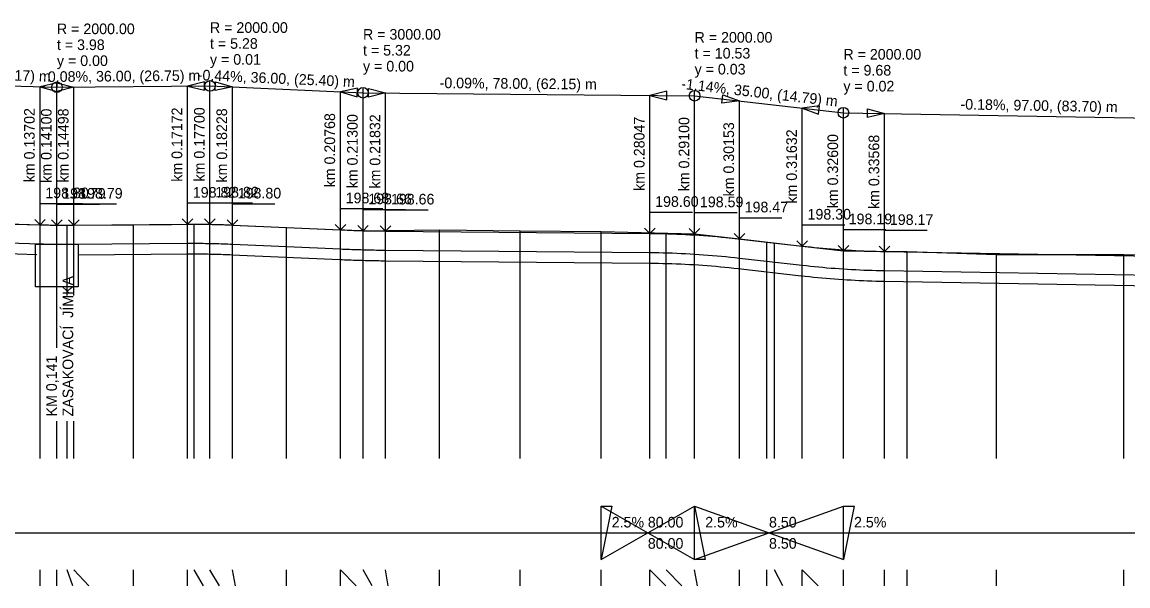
# Model space of a CAD drawing. Extents: x -51 to 53, y -74 to 15.
# Drawn here: x -25.16 to 0.85, y -60.55 to -47.28 of the extents above; entities that cross this region are included whole.
import ezdxf

# ---------------------------------------------------------------- set-up
doc = ezdxf.new("R2010")
doc.units = 0
for name, color, linetype in [('KONSTRUKCE_L', 7, 'Continuous'), ('KOTY_L', 7, 'Continuous'), ('Nová vrstva (0)', 7, 'Continuous'), ('PR_SKLON_L', 7, 'Continuous'), ('PR_SKLON_T', 7, 'Continuous'), ('SKLON_POMERY', 7, 'Continuous'), ('TEREN_L', 7, 'Continuous'), ('V_POLYGON', 7, 'Continuous'), ('V_POLYGON_ZO', 7, 'Continuous')]:
    doc.layers.add(name, color=color, linetype=linetype)

msp = doc.modelspace()

# ---------------------------------------------------------------- linework, layer by layer
at = {"layer": 'KONSTRUKCE_L'}
for p, q in [((-26.854, -52.432), (-24.738, -52.499)), ((-24.738, -52.499), (-24.698, -52.5)), ((-24.698, -52.5), (-24.658, -52.501)), ((-24.658, -52.501), (-24.618, -52.502)), ((-24.618, -52.502), (-24.579, -52.503)), ((-24.579, -52.503), (-24.539, -52.504)), ((-24.539, -52.504), (-24.499, -52.505)), ((-24.499, -52.505), (-24.459, -52.505)), ((-24.459, -52.505), (-24.42, -52.506)), ((-24.42, -52.506), (-24.38, -52.507)), ((-24.38, -52.507), (-24.34, -52.507)), ((-24.34, -52.507), (-24.3, -52.508)), ((-24.3, -52.508), (-24.26, -52.508)), ((-24.26, -52.508), (-24.221, -52.508)), ((-24.221, -52.508), (-24.181, -52.508)), ((-24.181, -52.508), (-24.141, -52.509)), ((-24.141, -52.509), (-24.101, -52.509)), ((-24.101, -52.509), (-24.062, -52.509)), ((-24.062, -52.509), (-24.022, -52.508)), ((-24.022, -52.508), (-23.982, -52.508)), ((-23.982, -52.508), (-23.942, -52.508)), ((-23.942, -52.508), (-21.268, -52.486)), ((-21.268, -52.486), (-21.215, -52.485)), ((-21.215, -52.485), (-21.162, -52.485)), ((-21.162, -52.485), (-21.109, -52.485)), ((-21.109, -52.485), (-21.057, -52.485)), ((-21.057, -52.485), (-21.004, -52.485)), ((-21.004, -52.485), (-20.951, -52.485)), ((-20.951, -52.485), (-20.898, -52.486)), ((-20.898, -52.486), (-20.846, -52.487)), ((-20.846, -52.487), (-20.793, -52.487)), ((-20.793, -52.487), (-20.74, -52.488)), ((-20.74, -52.488), (-20.687, -52.489)), ((-20.687, -52.489), (-20.634, -52.49)), ((-20.634, -52.49), (-20.582, -52.492)), ((-20.582, -52.492), (-20.529, -52.493)), ((-20.529, -52.493), (-20.476, -52.495)), ((-20.476, -52.495), (-20.423, -52.496)), ((-20.423, -52.496), (-20.371, -52.498)), ((-20.371, -52.498), (-20.318, -52.5)), ((-20.318, -52.5), (-20.265, -52.502)), ((-20.265, -52.502), (-20.212, -52.505)), ((-20.212, -52.505), (-17.672, -52.618)), ((-17.672, -52.618), (-17.619, -52.62)), ((-17.619, -52.62), (-17.566, -52.622)), ((-17.566, -52.622), (-17.512, -52.624)), ((-17.512, -52.624), (-17.459, -52.626)), ((-17.459, -52.626), (-17.406, -52.628)), ((-17.406, -52.628), (-17.353, -52.63)), ((-17.353, -52.63), (-17.3, -52.632)), ((-17.3, -52.632), (-17.246, -52.633)), ((-17.246, -52.633), (-17.193, -52.635)), ((-17.193, -52.635), (-17.14, -52.636)), ((-17.14, -52.636), (-17.087, -52.638)), ((-17.087, -52.638), (-17.034, -52.639)), ((-17.034, -52.639), (-16.98, -52.64)), ((-16.98, -52.64), (-16.927, -52.641)), ((-16.927, -52.641), (-16.874, -52.642)), ((-16.874, -52.642), (-16.821, -52.643)), ((-16.821, -52.643), (-16.768, -52.644)), ((-16.768, -52.644), (-16.714, -52.645)), ((-16.714, -52.645), (-16.661, -52.645)), ((-16.661, -52.645), (-16.608, -52.646)), ((-16.608, -52.646), (-10.393, -52.702)), ((-10.393, -52.702), (-10.288, -52.703)), ((-10.288, -52.703), (-10.182, -52.705)), ((-10.182, -52.705), (-10.077, -52.707)), ((-10.077, -52.707), (-9.972, -52.71)), ((-9.972, -52.71), (-9.867, -52.713)), ((-9.867, -52.713), (-9.761, -52.717)), ((-9.761, -52.717), (-9.656, -52.722)), ((-9.656, -52.722), (-9.551, -52.727)), ((-9.551, -52.727), (-9.445, -52.733)), ((-9.445, -52.733), (-9.34, -52.739)), ((-9.34, -52.739), (-9.235, -52.746)), ((-9.235, -52.746), (-9.129, -52.753)), ((-9.129, -52.753), (-9.024, -52.761)), ((-9.024, -52.761), (-8.919, -52.769)), ((-8.919, -52.769), (-8.813, -52.778)), ((-8.813, -52.778), (-8.708, -52.788)), ((-8.708, -52.788), (-8.603, -52.798)), ((-8.603, -52.798), (-8.498, -52.809)), ((-8.498, -52.809), (-8.392, -52.82)), ((-8.392, -52.82), (-8.287, -52.832)), ((-8.287, -52.832), (-6.808, -53.001)), ((-6.808, -53.001), (-6.711, -53.011)), ((-6.711, -53.011), (-6.614, -53.022)), ((-6.614, -53.022), (-6.517, -53.032)), ((-6.517, -53.032), (-6.421, -53.041)), ((-6.421, -53.041), (-6.324, -53.05)), ((-6.324, -53.05), (-6.227, -53.059)), ((-6.227, -53.059), (-6.13, -53.067)), ((-6.13, -53.067), (-6.034, -53.074)), ((-6.034, -53.074), (-5.937, -53.081)), ((-5.937, -53.081), (-5.84, -53.088)), ((-5.84, -53.088), (-5.743, -53.094)), ((-5.743, -53.094), (-5.646, -53.1)), ((-5.646, -53.1), (-5.55, -53.105)), ((-5.55, -53.105), (-5.453, -53.11)), ((-5.453, -53.11), (-5.356, -53.114)), ((-5.356, -53.114), (-5.259, -53.118)), ((-5.259, -53.118), (-5.163, -53.121)), ((-5.163, -53.121), (-5.066, -53.124)), ((-5.066, -53.124), (-4.969, -53.126)), ((-4.969, -53.126), (-4.872, -53.128)), ((-4.872, -53.128), (3.497, -53.275))]:
    msp.add_line(p, q, dxfattribs=at)
at = {"layer": 'KOTY_L'}
for p, q in [((-24.738, -57.551), (-24.738, -52.052)), ((-24.34, -54.944), (-24.34, -52.061)), ((-24.101, -53.716), (-24.101, -52.06)), ((-23.942, -53.716), (-23.942, -52.059)), ((-22.54, -57.551), (-22.54, -52.051)), ((-21.268, -57.551), (-21.268, -52.037)), ((-21.109, -57.551), (-21.109, -52.035)), ((-20.74, -57.551), (-20.74, -52.031)), ((-20.212, -57.551), (-20.212, -52.055)), ((-18.94, -57.551), (-18.94, -52.111)), ((-17.672, -57.551), (-17.672, -52.168)), ((-17.672, -57.551), (-17.672, -52.168)), ((-17.14, -57.551), (-17.14, -52.191)), ((-16.608, -57.551), (-16.608, -52.185)), ((-15.34, -57.551), (-15.34, -52.171)), ((-13.44, -57.551), (-13.44, -52.191)), ((-11.54, -57.551), (-11.54, -52.211)), ((-10.393, -57.551), (-10.393, -52.237)), ((-10.393, -57.551), (-10.393, -52.237)), ((-10.01, -57.551), (-10.01, -52.246)), ((-9.34, -57.551), (-9.34, -52.261)), ((-8.287, -57.551), (-8.287, -52.385)), ((-7.64, -57.551), (-7.64, -52.461)), ((-7.462, -57.551), (-7.462, -52.481)), ((-6.808, -57.551), (-6.808, -52.554)), ((-6.808, -57.551), (-6.808, -52.554)), ((-5.84, -57.551), (-5.84, -52.661)), ((-4.872, -57.551), (-4.872, -52.674)), ((-4.34, -57.551), (-4.34, -52.681)), ((-2.24, -57.551), (-2.24, -52.751)), ((0.76, -57.551), (0.76, -52.751)), ((-24.34, -57.551), (-24.34, -56.675)), ((-24.101, -57.551), (-24.101, -56.675)), ((-23.942, -57.551), (-23.942, -56.675)), ((-24.738, -60.551), (-24.738, -60.176)), ((-24.34, -60.551), (-24.34, -60.176)), ((-23.965, -60.551), (-24.101, -60.176)), ((-23.59, -60.551), (-23.942, -60.176)), ((-22.54, -60.551), (-22.54, -60.176)), ((-21.268, -60.551), (-21.268, -60.176)), ((-20.893, -60.551), (-21.109, -60.176)), ((-20.518, -60.551), (-20.74, -60.176)), ((-20.143, -60.551), (-20.212, -60.176)), ((-18.94, -60.551), (-18.94, -60.176)), ((-17.672, -60.551), (-17.672, -60.176)), ((-17.297, -60.551), (-17.672, -60.176)), ((-16.922, -60.551), (-17.14, -60.176)), ((-16.547, -60.551), (-16.608, -60.176)), ((-15.34, -60.551), (-15.34, -60.176)), ((-13.44, -60.551), (-13.44, -60.176)), ((-11.54, -60.551), (-11.54, -60.176)), ((-10.393, -60.551), (-10.393, -60.176)), ((-10.018, -60.551), (-10.393, -60.176)), ((-9.643, -60.551), (-10.01, -60.176)), ((-9.268, -60.551), (-9.34, -60.176)), ((-8.287, -60.551), (-8.287, -60.176)), ((-7.64, -60.551), (-7.64, -60.176)), ((-7.265, -60.551), (-7.462, -60.176)), ((-6.808, -60.551), (-6.808, -60.176)), ((-6.433, -60.551), (-6.808, -60.176)), ((-5.84, -60.551), (-5.84, -60.176)), ((-4.872, -60.551), (-4.872, -60.176)), ((-4.34, -60.551), (-4.34, -60.176)), ((-2.24, -60.551), (-2.24, -60.176)), ((0.76, -60.551), (0.76, -60.176))]:
    msp.add_line(p, q, dxfattribs=at)
at = {"layer": 'Nová vrstva (0)'}
for p, q in [((-26.862, -52.682), (-24.816, -52.746)), ((-23.842, -52.757), (-21.266, -52.736)), ((-21.266, -52.736), (-21.213, -52.735)), ((-21.214, -52.735), (-21.161, -52.735)), ((-21.162, -52.735), (-21.109, -52.735)), ((-21.11, -52.735), (-21.057, -52.735)), ((-21.058, -52.735), (-21.005, -52.735)), ((-21.005, -52.735), (-20.953, -52.735)), ((-20.953, -52.735), (-20.901, -52.736)), ((-20.901, -52.736), (-20.848, -52.737)), ((-20.849, -52.737), (-20.796, -52.737)), ((-20.797, -52.737), (-20.744, -52.738)), ((-20.745, -52.738), (-20.692, -52.739)), ((-20.693, -52.739), (-20.64, -52.74)), ((-20.641, -52.74), (-20.588, -52.742)), ((-20.588, -52.742), (-20.536, -52.743)), ((-20.536, -52.743), (-20.484, -52.745)), ((-20.484, -52.745), (-20.431, -52.746)), ((-20.432, -52.746), (-20.379, -52.748)), ((-20.38, -52.748), (-20.327, -52.75)), ((-20.328, -52.75), (-20.275, -52.752)), ((-20.276, -52.752), (-20.223, -52.754)), ((-20.223, -52.754), (-17.683, -52.867)), ((-17.683, -52.867), (-17.63, -52.87)), ((-17.629, -52.87), (-17.576, -52.872)), ((-17.576, -52.872), (-17.522, -52.874)), ((-17.522, -52.874), (-17.469, -52.876)), ((-17.468, -52.876), (-17.415, -52.878)), ((-17.415, -52.878), (-17.361, -52.88)), ((-17.361, -52.88), (-17.308, -52.882)), ((-17.307, -52.882), (-17.254, -52.883)), ((-17.254, -52.883), (-17.201, -52.885)), ((-17.2, -52.885), (-17.147, -52.886)), ((-17.146, -52.886), (-17.093, -52.888)), ((-17.093, -52.888), (-17.04, -52.889)), ((-17.039, -52.889), (-16.986, -52.89)), ((-16.986, -52.89), (-16.932, -52.891)), ((-16.932, -52.891), (-16.879, -52.892)), ((-16.878, -52.892), (-16.825, -52.893)), ((-16.825, -52.893), (-16.771, -52.894)), ((-16.771, -52.894), (-16.718, -52.895)), ((-16.717, -52.895), (-16.664, -52.895)), ((-16.664, -52.895), (-16.61, -52.896)), ((-16.61, -52.896), (-10.395, -52.952)), ((-10.396, -52.952), (-10.291, -52.953)), ((-10.292, -52.953), (-10.187, -52.955)), ((-10.188, -52.955), (-10.083, -52.957)), ((-10.084, -52.957), (-9.979, -52.96)), ((-9.98, -52.96), (-9.875, -52.963)), ((-9.876, -52.963), (-9.771, -52.967)), ((-9.772, -52.967), (-9.667, -52.972)), ((-9.668, -52.972), (-9.563, -52.977)), ((-9.564, -52.977), (-9.459, -52.982)), ((-9.46, -52.982), (-9.355, -52.988)), ((-9.356, -52.988), (-9.251, -52.995)), ((-9.252, -52.995), (-9.147, -53.002)), ((-9.148, -53.002), (-9.043, -53.01)), ((-9.044, -53.01), (-8.939, -53.019)), ((-8.94, -53.018), (-8.835, -53.027)), ((-8.836, -53.027), (-8.731, -53.037)), ((-8.732, -53.037), (-8.627, -53.047)), ((-8.628, -53.047), (-8.523, -53.057)), ((-8.524, -53.057), (-8.419, -53.068)), ((-8.42, -53.068), (-8.315, -53.08)), ((-8.315, -53.08), (-6.836, -53.249)), ((-6.835, -53.249), (-6.739, -53.26)), ((-6.737, -53.26), (-6.641, -53.27)), ((-6.639, -53.27), (-6.543, -53.28)), ((-6.542, -53.28), (-6.445, -53.29)), ((-6.444, -53.29), (-6.347, -53.299)), ((-6.346, -53.299), (-6.249, -53.308)), ((-6.248, -53.308), (-6.151, -53.316)), ((-6.15, -53.316), (-6.053, -53.323)), ((-6.052, -53.323), (-5.955, -53.331)), ((-5.954, -53.331), (-5.857, -53.337)), ((-5.856, -53.337), (-5.759, -53.343)), ((-5.758, -53.343), (-5.661, -53.349)), ((-5.66, -53.349), (-5.563, -53.354)), ((-5.562, -53.355), (-5.465, -53.359)), ((-5.464, -53.359), (-5.367, -53.364)), ((-5.366, -53.364), (-5.269, -53.367)), ((-5.268, -53.367), (-5.171, -53.371)), ((-5.17, -53.371), (-5.073, -53.374)), ((-5.072, -53.374), (-4.975, -53.376)), ((-4.974, -53.376), (-4.877, -53.378)), ((-4.877, -53.378), (3.493, -53.525))]:
    msp.add_line(p, q, dxfattribs=at)
msp.add_lwpolyline([(-24.84, -52.508), (-23.84, -52.508), (-23.84, -53.508), (-24.84, -53.508)], close=True, dxfattribs=at)
at = {"layer": 'PR_SKLON_L'}
for p, q in [((-11.54, -59.926), (-9.34, -58.676)), ((-11.54, -58.676), (-9.34, -59.926)), ((-9.34, -59.926), (-5.84, -58.676)), ((-9.34, -58.676), (-5.84, -59.926)), ((-38.44, -59.301), (-11.54, -59.301)), ((-11.54, -59.301), (-9.34, -59.301)), ((-9.34, -59.301), (-5.84, -59.301)), ((-5.84, -59.301), (3.86, -59.301)), ((-9.34, -59.926), (-9.34, -59.926)), ((-5.84, -59.926), (-5.84, -59.926))]:
    msp.add_line(p, q, dxfattribs=at)
for points in [[(-11.54, -59.301), (-11.54, -58.676), (-11.29, -58.676), (-11.54, -59.926)], [(-9.34, -59.301), (-9.34, -58.676), (-9.09, -59.926), (-9.34, -59.926)], [(-5.84, -59.301), (-5.84, -58.676), (-5.59, -58.676), (-5.84, -59.926)]]:
    msp.add_lwpolyline(points, close=True, dxfattribs=at)
at = {"layer": 'SKLON_POMERY'}
for p, q in [((-27.84, -48.701), (-24.34, -48.811)), ((-24.738, -52.049), (-24.738, -48.799)), ((-24.34, -48.811), (-24.34, -48.686)), ((-24.34, -48.811), (-20.74, -48.781)), ((-24.34, -52.061), (-24.34, -48.811)), ((-23.942, -52.058), (-23.942, -48.808)), ((-21.268, -52.036), (-21.268, -48.786)), ((-20.74, -48.781), (-20.74, -48.656)), ((-20.74, -52.031), (-20.74, -48.781)), ((-20.74, -48.781), (-17.14, -48.941)), ((-20.212, -52.055), (-20.212, -48.805)), ((-17.14, -48.941), (-17.14, -48.816)), ((-9.34, -49.011), (-9.34, -48.886)), ((-17.672, -52.168), (-17.672, -48.918)), ((-17.14, -52.191), (-17.14, -48.941)), ((-17.14, -48.941), (-9.34, -49.011)), ((-16.608, -52.196), (-16.608, -48.946)), ((-10.393, -52.252), (-10.393, -49.002)), ((-9.34, -52.261), (-9.34, -49.011)), ((-9.34, -49.011), (-5.84, -49.411)), ((-8.287, -52.382), (-8.287, -49.132)), ((-6.808, -52.551), (-6.808, -49.301)), ((-5.84, -49.411), (-5.84, -49.286)), ((-5.84, -52.661), (-5.84, -49.411)), ((-5.84, -49.411), (3.86, -49.581)), ((-4.872, -52.678), (-4.872, -49.428))]:
    msp.add_line(p, q, dxfattribs=at)
for points in [[(-24.738, -48.799), (-24.341, -48.911), (-24.335, -48.711), (-24.738, -48.799)], [(-23.942, -48.808), (-24.342, -48.911), (-24.343, -48.711), (-23.942, -48.808)], [(-21.268, -48.786), (-20.867, -48.882), (-20.869, -48.682), (-21.268, -48.786)], [(-20.212, -48.805), (-20.616, -48.887), (-20.607, -48.687), (-20.212, -48.805)], [(-17.672, -48.918), (-17.277, -49.035), (-17.268, -48.835), (-17.672, -48.918)], [(-16.608, -48.946), (-17.009, -49.042), (-17.007, -48.842), (-16.608, -48.946)], [(-10.393, -49.002), (-9.994, -49.105), (-9.992, -48.905), (-10.393, -49.002)], [(-8.287, -49.132), (-8.696, -49.185), (-8.673, -48.987), (-8.287, -49.132)], [(-6.808, -49.301), (-6.422, -49.445), (-6.399, -49.247), (-6.808, -49.301)], [(-4.872, -49.428), (-5.274, -49.521), (-5.271, -49.321), (-4.872, -49.428)]]:
    msp.add_lwpolyline(points, close=True, dxfattribs=at)
for points in [[(-24.863, -51.924), (-24.738, -52.049), (-24.613, -51.924), (-24.738, -52.049), (-24.738, -51.549), (-23.738, -51.549)], [(-24.465, -51.936), (-24.34, -52.061), (-24.215, -51.936), (-24.34, -52.061), (-24.34, -51.561), (-23.34, -51.561)], [(-24.067, -51.933), (-23.942, -52.058), (-23.817, -51.933), (-23.942, -52.058), (-23.942, -51.558), (-22.942, -51.558)], [(-21.393, -51.911), (-21.268, -52.036), (-21.143, -51.911), (-21.268, -52.036), (-21.268, -51.536), (-20.268, -51.536)], [(-20.865, -51.906), (-20.74, -52.031), (-20.615, -51.906), (-20.74, -52.031), (-20.74, -51.531), (-19.74, -51.531)], [(-20.337, -51.93), (-20.212, -52.055), (-20.087, -51.93), (-20.212, -52.055), (-20.212, -51.555), (-19.212, -51.555)], [(-17.797, -52.043), (-17.672, -52.168), (-17.547, -52.043), (-17.672, -52.168), (-17.672, -51.668), (-16.672, -51.668)], [(-17.265, -52.066), (-17.14, -52.191), (-17.015, -52.066), (-17.14, -52.191), (-17.14, -51.691), (-16.14, -51.691)], [(-16.733, -52.071), (-16.608, -52.196), (-16.483, -52.071), (-16.608, -52.196), (-16.608, -51.696), (-15.608, -51.696)], [(-10.518, -52.127), (-10.393, -52.252), (-10.268, -52.127), (-10.393, -52.252), (-10.393, -51.752), (-9.393, -51.752)], [(-9.465, -52.136), (-9.34, -52.261), (-9.215, -52.136), (-9.34, -52.261), (-9.34, -51.761), (-8.34, -51.761)], [(-8.412, -52.257), (-8.287, -52.382), (-8.162, -52.257), (-8.287, -52.382), (-8.287, -51.882), (-7.287, -51.882)], [(-6.933, -52.426), (-6.808, -52.551), (-6.683, -52.426), (-6.808, -52.551), (-6.808, -52.051), (-5.808, -52.051)], [(-5.965, -52.536), (-5.84, -52.661), (-5.715, -52.536), (-5.84, -52.661), (-5.84, -52.161), (-4.84, -52.161)], [(-4.997, -52.553), (-4.872, -52.678), (-4.747, -52.553), (-4.872, -52.678), (-4.872, -52.178), (-3.872, -52.178)]]:
    msp.add_lwpolyline(points, dxfattribs=at)
for centre in [(-24.34, -48.811), (-20.74, -48.781), (-17.14, -48.941), (-9.34, -49.011), (-5.84, -49.411)]:
    msp.add_circle(centre, 0.125, dxfattribs=at)
at = {"layer": 'TEREN_L'}
for p, q in [((-26.14, -52.021), (-24.34, -52.061)), ((-24.34, -52.061), (-22.54, -52.051)), ((-22.54, -52.051), (-20.74, -52.031)), ((-20.74, -52.031), (-18.94, -52.111)), ((-18.94, -52.111), (-17.14, -52.191)), ((-17.14, -52.191), (-15.34, -52.171)), ((-15.34, -52.171), (-13.44, -52.191)), ((-13.44, -52.191), (-11.54, -52.211)), ((-11.54, -52.211), (-9.34, -52.261)), ((-9.34, -52.261), (-7.64, -52.461)), ((-7.64, -52.461), (-5.84, -52.661)), ((-5.84, -52.661), (-4.34, -52.681)), ((-4.34, -52.681), (-2.24, -52.751)), ((-2.24, -52.751), (0.76, -52.751)), ((0.76, -52.751), (3.86, -52.831))]:
    msp.add_line(p, q, dxfattribs=at)
at = {"layer": 'V_POLYGON'}
for p, q in [((-26.854, -51.982), (-24.738, -52.049)), ((-23.942, -52.058), (-21.268, -52.036)), ((-20.212, -52.055), (-17.672, -52.168)), ((-16.608, -52.196), (-10.393, -52.252)), ((-8.287, -52.382), (-6.808, -52.551)), ((-4.872, -52.678), (3.497, -52.825))]:
    msp.add_line(p, q, dxfattribs=at)
for points in [[(-24.738, -52.049), (-24.698, -52.05), (-24.658, -52.051), (-24.618, -52.052), (-24.579, -52.053), (-24.539, -52.054), (-24.499, -52.055), (-24.459, -52.055), (-24.42, -52.056), (-24.38, -52.057), (-24.34, -52.057), (-24.3, -52.058), (-24.26, -52.058), (-24.221, -52.058), (-24.181, -52.058), (-24.141, -52.059), (-24.101, -52.059), (-24.062, -52.059), (-24.022, -52.058), (-23.982, -52.058), (-23.942, -52.058)], [(-21.268, -52.036), (-21.215, -52.035), (-21.162, -52.035), (-21.109, -52.035), (-21.057, -52.035), (-21.004, -52.035), (-20.951, -52.035), (-20.898, -52.036), (-20.846, -52.037), (-20.793, -52.037), (-20.74, -52.038), (-20.687, -52.039), (-20.634, -52.04), (-20.582, -52.042), (-20.529, -52.043), (-20.476, -52.045), (-20.423, -52.046), (-20.371, -52.048), (-20.318, -52.05), (-20.265, -52.052), (-20.212, -52.055)], [(-17.672, -52.168), (-17.619, -52.17), (-17.566, -52.172), (-17.512, -52.174), (-17.459, -52.176), (-17.406, -52.178), (-17.353, -52.18), (-17.3, -52.182), (-17.246, -52.183), (-17.193, -52.185), (-17.14, -52.186), (-17.087, -52.188), (-17.034, -52.189), (-16.98, -52.19), (-16.927, -52.191), (-16.874, -52.192), (-16.821, -52.193), (-16.768, -52.194), (-16.714, -52.195), (-16.661, -52.195), (-16.608, -52.196)], [(-10.393, -52.252), (-10.288, -52.253), (-10.182, -52.255), (-10.077, -52.257), (-9.972, -52.26), (-9.867, -52.263), (-9.761, -52.267), (-9.656, -52.272), (-9.551, -52.277), (-9.445, -52.283), (-9.34, -52.289), (-9.235, -52.296), (-9.129, -52.303), (-9.024, -52.311), (-8.919, -52.319), (-8.813, -52.328), (-8.708, -52.338), (-8.603, -52.348), (-8.498, -52.359), (-8.392, -52.37), (-8.287, -52.382)], [(-6.808, -52.551), (-6.711, -52.561), (-6.614, -52.572), (-6.517, -52.582), (-6.421, -52.591), (-6.324, -52.6), (-6.227, -52.609), (-6.13, -52.617), (-6.034, -52.624), (-5.937, -52.631), (-5.84, -52.638), (-5.743, -52.644), (-5.646, -52.65), (-5.55, -52.655), (-5.453, -52.66), (-5.356, -52.664), (-5.259, -52.668), (-5.163, -52.671), (-5.066, -52.674), (-4.969, -52.676), (-4.872, -52.678)]]:
    msp.add_lwpolyline(points, dxfattribs=at)
at = {"layer": 'V_POLYGON_ZO'}
for p, q in [((-24.738, -52.049), (-24.34, -52.061)), ((-24.34, -52.061), (-23.942, -52.058)), ((-21.268, -52.036), (-20.74, -52.031)), ((-20.74, -52.031), (-20.212, -52.055)), ((-17.672, -52.168), (-17.14, -52.191)), ((-17.14, -52.191), (-16.608, -52.196)), ((-10.393, -52.252), (-9.34, -52.261)), ((-9.34, -52.261), (-8.287, -52.382)), ((-6.808, -52.551), (-5.84, -52.661)), ((-5.84, -52.661), (-4.872, -52.678))]:
    msp.add_line(p, q, dxfattribs=at)

# ---------------------------------------------------------------- texts
at = {"layer": 'Nová vrstva (0)'}
for s, p in [('ZASAKOVACÍ  JÍMKA', (-23.957, -56.561)), ('KM 0,141', (-24.341, -56.561))]:
    msp.add_text(s, height=0.25, rotation=90, dxfattribs=at).set_placement(p)
at = {"layer": 'PR_SKLON_T'}
for s, p in [('2.5%', (-11.29, -59.176)), ('80.00', (-10.44, -59.176)), ('2.5%', (-9.09, -59.176)), ('8.50', (-7.59, -59.176)), ('2.5%', (-5.59, -59.176)), ('80.00', (-10.44, -59.676)), ('8.50', (-7.59, -59.676))]:
    msp.add_text(s, height=0.25, dxfattribs=at).set_placement(p)
at = {"layer": 'SKLON_POMERY'}
for s, p in [('R = 2000.00', (-24.34, -47.561)), ('R = 2000.00', (-20.74, -47.531)), ('R = 3000.00', (-17.14, -47.691)), ('R = 2000.00', (-9.34, -47.761)), ('t = 3.98', (-24.34, -47.936)), ('t = 5.28', (-20.74, -47.906)), ('t = 5.32', (-17.14, -48.066)), ('y = 0.00', (-24.34, -48.311)), ('y = 0.01', (-20.74, -48.281)), ('t = 10.53', (-9.34, -48.136)), ('R = 2000.00', (-5.84, -48.161)), ('y = 0.00', (-17.14, -48.441)), ('y = 0.03', (-9.34, -48.511)), ('t = 9.68', (-5.84, -48.536)), ('y = 0.02', (-5.84, -48.911)), ('198.80', (-24.613, -51.424)), ('198.79', (-24.215, -51.436)), ('198.79', (-23.817, -51.433)), ('198.82', (-21.143, -51.411)), ('198.82', (-20.615, -51.406)), ('198.80', (-20.087, -51.43)), ('198.68', (-17.547, -51.543)), ('198.66', (-17.015, -51.566)), ('198.66', (-16.483, -51.571)), ('198.60', (-10.268, -51.627)), ('198.59', (-9.215, -51.636)), ('198.47', (-8.162, -51.757)), ('198.30', (-6.683, -51.926)), ('198.19', (-5.715, -52.036)), ('198.17', (-4.747, -52.053))]:
    msp.add_text(s, height=0.25, dxfattribs=at).set_placement(p)
for s, rotation, p in [('-0.31%, 35.00, (21.17) m', 358.1999, (-28.185, -48.565)), ('0.08%, 36.00, (26.75) m', 0.4774, (-24.553, -48.688)), ('-0.44%, 36.00, (25.40) m', 357.4552, (-21.032, -48.643)), ('-0.09%, 78.00, (62.15) m', 359.4858, (-15.339, -48.832)), ('-1.14%, 35.00, (14.79) m', 353.4802, (-9.662, -48.847)), ('-0.18%, 97.00, (83.70) m', 358.9959, (-3.087, -49.334)), ('km 0.13702', 90, (-24.863, -51.049)), ('km 0.14100', 90, (-24.465, -51.061)), ('km 0.14498', 90, (-24.067, -51.058)), ('km 0.17172', 90, (-21.393, -51.036)), ('km 0.17700', 90, (-20.865, -51.031)), ('km 0.18228', 90, (-20.337, -51.055)), ('km 0.20768', 90, (-17.797, -51.168)), ('km 0.21300', 90, (-17.265, -51.191)), ('km 0.21832', 90, (-16.733, -51.196)), ('km 0.28047', 90, (-10.518, -51.252)), ('km 0.29100', 90, (-9.465, -51.261)), ('km 0.30153', 90, (-8.412, -51.382)), ('km 0.31632', 90, (-6.933, -51.551)), ('km 0.32600', 90, (-5.965, -51.661)), ('km 0.33568', 90, (-4.997, -51.678))]:
    msp.add_text(s, height=0.25, rotation=rotation, dxfattribs=at).set_placement(p)

doc.saveas('drawing.dxf')
